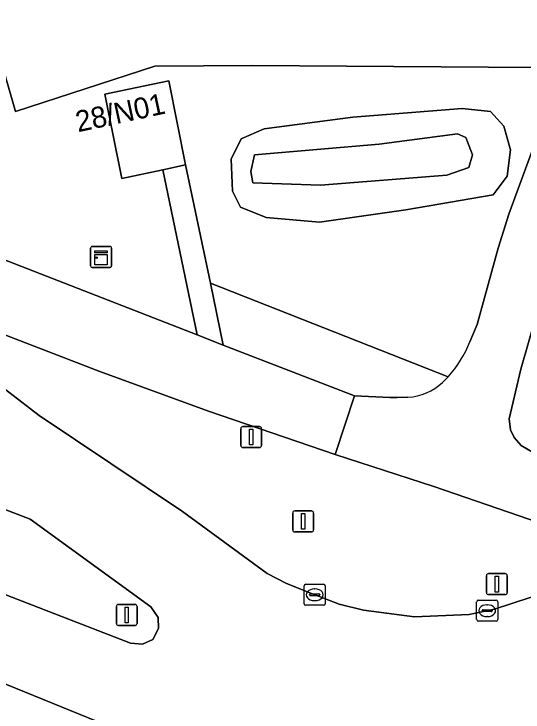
# Model space of a CAD drawing. Extents: x 156141 to 158132, y 385651 to 388333.
# Drawn here: x 156302.91 to 156327.12, y 386506.29 to 386539.53 of the extents above; entities that cross this region are included whole.
import ezdxf

# ---------------------------------------------------------------- set-up
doc = ezdxf.new("R2010")
doc.units = 0
for name, color, linetype in [('IMGEO_Berm_groen', 7, 'Continuous'), ('IMGEO_Bouwland', 7, 'Continuous'), ('IMGEO_Fietspad_gesloten', 7, 'Continuous'), ('IMGEO_Groenvoorziening', 7, 'Continuous'), ('IMGEO_Kast', 7, 'Continuous'), ('IMGEO_Kolk', 7, 'Continuous'), ('IMGEO_Lichtmast', 7, 'Continuous'), ('IMGEO_Pand', 7, 'Continuous'), ('IMGEO_Pand_nummerreeks', 7, 'Continuous'), ('IMGEO_Rijbaan_lokaal_gesloten', 7, 'Continuous'), ('IMGEO_Verkeersbordpaal', 7, 'Continuous'), ('IMGEO_Verkeerseiland_open', 7, 'Continuous'), ('IMGEO_Voetpad_open', 7, 'Continuous')]:
    doc.layers.add(name, color=color, linetype=linetype)

msp = doc.modelspace()

# ---------------------------------------------------------------- linework, layer by layer
at = {"layer": 'IMGEO_Berm_groen'}
for points in [[(156329, 386529.519), (156327.01, 386522.618), (156326.464, 386520.258), (156326.529, 386519.727), (156326.698, 386519.369), (156327.033, 386518.98), (156327.569, 386518.673)], [(156312.247, 386526.707), (156312.861, 386523.766), (156319.111, 386521.349), (156320.786, 386521.275), (156321.133, 386521.268), (156321.646, 386521.284)], [(156323.283, 386521.987), (156323.558, 386522.259), (156312.247, 386526.707)], [(156330.955, 386514.254), (156322.883, 386517.032), (156318.18, 386518.557), (156312.164, 386520.621), (156306.982, 386522.509), (156300.726, 386524.92)], [(156302.029, 386522.003), (156304.102, 386520.406), (156310.923, 386515.834), (156314.943, 386512.888), (156315.868, 386512.406), (156317.104, 386511.915), (156318.366, 386511.435), (156319.539, 386511.139), (156321.96, 386510.826), (156324.552, 386510.938), (156325.767, 386511.191), (156328.331, 386512.037)], [(156312.749, 386503.448), (156300.816, 386508.304), (156300.112, 386507.623), (156298.483, 386509.171), (156297.512, 386509.849), (156296.614, 386510.333), (156294.594, 386511.201), (156294.457, 386511.254), (156293.331, 386511.691), (156280.601, 386516.602), (156280.646, 386516.287), (156293.375, 386511.374), (156294.501, 386510.945), (156294.638, 386510.893), (156295.217, 386510.672), (156294.81, 386509.685), (156294.714, 386509.453), (156294.56, 386509.081), (156293.654, 386509.429), (156280.922, 386514.32), (156281.324, 386511.45), (156294.12, 386506.497), (156295.193, 386506.082)]]:
    msp.add_lwpolyline(points, dxfattribs=at)
msp.add_arc((156321.502, 386523.877), 2.597, 273.1821, 313.2995, dxfattribs=at)
at = {"layer": 'IMGEO_Bouwland'}
msp.add_lwpolyline([(156298.424, 386578.759), (156299.096, 386571.593), (156300.523, 386561.055), (156301.816, 386553.654), (156301.952, 386551.718), (156300.78, 386542.538), (156302.98, 386534.895), (156309.604, 386537.043), (156314.236, 386537.081), (156327.718, 386536.986), (156337.845, 386577.757)], dxfattribs=at)
at = {"layer": 'IMGEO_Fietspad_gesloten'}
for points in [[(156348.163, 386611.714), (156343.943, 386590.004), (156341.252, 386578.081), (156338.908, 386569.228), (156337.052, 386561.839), (156334.06, 386550.854), (156331.742, 386543.951), (156329.901, 386538.856), (156329.08, 386536.913), (156328.367, 386535.225), (156326.447, 386529.996), (156325.935, 386528.385), (156324.936, 386524.744), (156324.596, 386523.924)], [(156327.569, 386518.673), (156327.033, 386518.98), (156326.698, 386519.369), (156326.529, 386519.727), (156326.464, 386520.258), (156327.01, 386522.618), (156329, 386529.519)], [(156323.558, 386522.259), (156323.283, 386521.987)], [(156321.646, 386521.284), (156321.133, 386521.268), (156320.786, 386521.275), (156319.111, 386521.349), (156318.18, 386518.557), (156322.883, 386517.032), (156330.955, 386514.254)]]:
    msp.add_lwpolyline(points, dxfattribs=at)
msp.add_lwpolyline([(156278.184, 386533.831), (156290.97, 386528.872), (156292.011, 386528.468), (156292.144, 386528.416), (156292.75, 386528.181), (156300.726, 386524.92), (156306.982, 386522.509), (156312.164, 386520.621), (156318.18, 386518.557), (156319.111, 386521.349), (156312.861, 386523.766), (156311.622, 386524.249), (156299.915, 386528.814), (156295.216, 386530.406), (156291.691, 386531.601), (156291.559, 386531.654), (156290.488, 386532.081), (156277.717, 386537.157), (156277.717, 386537.157)], close=True, dxfattribs=at)
for centre, radius, start, end in [((156319.467, 386525.966), 5.521, 317.8239, 338.2954), ((156321.502, 386523.877), 2.597, 273.1821, 313.2995)]:
    msp.add_arc(centre, radius, start, end, dxfattribs=at)
at = {"layer": 'IMGEO_Groenvoorziening'}
for points in [[(156324.596, 386523.924), (156324.936, 386524.744), (156325.935, 386528.385), (156326.447, 386529.996), (156328.367, 386535.225), (156329.08, 386536.913), (156327.718, 386536.986), (156314.236, 386537.081), (156309.604, 386537.043), (156302.98, 386534.895), (156300.78, 386542.538), (156301.952, 386551.718), (156301.606, 386551.306), (156300.28, 386551.079), (156300.198, 386551.075), (156298.812, 386551.003), (156297.818, 386551.756), (156295.883, 386563.923), (156294.043, 386576.864)], [(156277.528, 386538.5), (156277.717, 386537.157), (156277.717, 386537.157), (156290.488, 386532.081), (156291.559, 386531.654), (156291.691, 386531.601), (156295.216, 386530.406), (156296.507, 386533.719), (156301.125, 386531.917), (156299.915, 386528.814), (156311.622, 386524.249), (156309.985, 386532.114), (156308.042, 386531.705), (156307.234, 386535.712), (156310.277, 386536.35), (156311.07, 386532.343), (156312.247, 386526.707), (156323.558, 386522.259)]]:
    msp.add_lwpolyline(points, dxfattribs=at)
for points in [[(156321.551, 386530.208), (156325.692, 386530.921), (156326.359, 386531.817), (156326.521, 386533.069), (156326.203, 386534.188), (156325.576, 386534.896), (156324.217, 386535.031), (156319.03, 386534.625), (156314.803, 386534.068), (156313.717, 386533.589), (156313.239, 386532.618), (156313.301, 386531.095), (156313.679, 386530.328), (156314.905, 386529.836), (156317.436, 386529.624)], [(156324.217, 386535.031), (156325.576, 386534.896), (156326.203, 386534.188), (156326.521, 386533.069), (156326.359, 386531.817), (156325.692, 386530.921), (156321.551, 386530.208), (156317.436, 386529.624), (156314.905, 386529.836), (156313.679, 386530.328), (156313.301, 386531.095), (156313.239, 386532.618), (156313.717, 386533.589), (156314.803, 386534.068), (156319.03, 386534.625)], [(156323.498, 386531.855), (156324.54, 386532.22), (156324.723, 386532.819), (156324.395, 386533.645), (156323.996, 386533.828), (156320.273, 386533.334), (156314.349, 386532.826), (156314.165, 386532.027), (156314.267, 386531.49), (156317.48, 386531.375)], [(156317.48, 386531.375), (156314.267, 386531.49), (156314.165, 386532.027), (156314.349, 386532.826), (156320.273, 386533.334), (156323.996, 386533.828), (156324.395, 386533.645), (156324.723, 386532.819), (156324.54, 386532.22), (156323.498, 386531.855)]]:
    msp.add_lwpolyline(points, close=True, dxfattribs=at)
msp.add_arc((156319.467, 386525.966), 5.521, 317.8239, 338.2954, dxfattribs=at)
at = {"layer": 'IMGEO_Kast'}
for p, q in [((156306.55, 386527.536), (156306.55, 386528.377)), ((156306.55, 386528.377), (156306.55, 386527.536)), ((156306.625, 386528.461), (156307.466, 386528.461)), ((156307.466, 386528.461), (156306.625, 386528.461)), ((156307.55, 386528.386), (156307.55, 386527.545)), ((156307.55, 386527.545), (156307.55, 386528.386)), ((156307.475, 386527.461), (156306.634, 386527.461)), ((156306.634, 386527.461), (156307.475, 386527.461))]:
    msp.add_line(p, q, dxfattribs=at)
for points in [[(156306.745, 386528.251), (156307.345, 386528.251), (156307.345, 386528.166), (156306.745, 386528.166), (156306.745, 386528.251)], [(156306.745, 386528.076), (156307.345, 386528.076), (156307.345, 386527.587), (156306.745, 386527.587), (156306.745, 386528.076)]]:
    msp.add_lwpolyline(points, dxfattribs=at)
msp.add_circle((156306.829, 386527.925), 0.0377, dxfattribs=at)
for centre, start, end in [((156306.628, 386528.383), 92.4484, 184.2845), ((156306.628, 386528.383), 92.4484, 184.2845), ((156307.472, 386528.383), 2.4484, 94.2845), ((156307.472, 386528.383), 2.4484, 94.2845), ((156306.628, 386527.539), 182.4484, 274.2845), ((156306.628, 386527.539), 182.4484, 274.2845), ((156307.472, 386527.539), 272.4484, 4.2845), ((156307.472, 386527.539), 272.4484, 4.2845)]:
    msp.add_arc(centre, 0.0779, start, end, dxfattribs=at)
at = {"layer": 'IMGEO_Kolk'}
for p, q in [((156316.784, 386512.375), (156317.636, 386512.375)), ((156316.709, 386511.449), (156316.709, 386512.301)), ((156317.197, 386512.155), (156317.222, 386512.155)), ((156317.71, 386512.301), (156317.71, 386511.449)), ((156316.968, 386511.869), (156316.968, 386511.881)), ((156317.406, 386511.832), (156317.008, 386511.832)), ((156317.011, 386511.918), (156317.409, 386511.918)), ((156317.452, 386511.881), (156317.452, 386511.869)), ((156317.636, 386511.375), (156316.784, 386511.375)), ((156317.22, 386511.595), (156317.195, 386511.595)), ((156324.914, 386510.692), (156324.914, 386511.544)), ((156324.989, 386511.618), (156325.841, 386511.618)), ((156325.402, 386511.398), (156325.427, 386511.398)), ((156325.915, 386511.544), (156325.915, 386510.692)), ((156325.173, 386511.112), (156325.173, 386511.124)), ((156325.611, 386511.075), (156325.213, 386511.075)), ((156325.216, 386511.161), (156325.614, 386511.161)), ((156325.657, 386511.124), (156325.657, 386511.112)), ((156325.425, 386510.838), (156325.4, 386510.838)), ((156325.841, 386510.618), (156324.989, 386510.618))]:
    msp.add_line(p, q, dxfattribs=at)
for points in [[(156316.784, 386512.375), (156317.636, 386512.375)], [(156316.709, 386511.449), (156316.709, 386512.301)], [(156317.71, 386512.301), (156317.71, 386511.449)], [(156317.636, 386511.375), (156316.784, 386511.375)], [(156324.914, 386510.692), (156324.914, 386511.544)], [(156324.989, 386511.618), (156325.841, 386511.618)], [(156325.915, 386511.544), (156325.915, 386510.692)], [(156325.841, 386510.618), (156324.989, 386510.618)]]:
    msp.add_lwpolyline(points, dxfattribs=at)
for centre, radius, start, end in [((156316.786, 386512.299), 0.0765, 91.552, 178.448), ((156316.786, 386512.299), 0.0765, 91.552, 178.448), ((156317.634, 386512.299), 0.0765, 1.552, 88.448), ((156317.634, 386512.299), 0.0765, 1.552, 88.448), ((156317.008, 386511.878), 0.0403, 85.8775, 175.7526), ((156317.005, 386511.868), 0.0366, 178.938, 274.7102), ((156317.409, 386511.875), 0.043, 264.8664, 352.4533), ((156317.413, 386511.88), 0.0386, 1.7309, 96.639), ((156316.786, 386511.451), 0.0765, 181.552, 268.448), ((156316.786, 386511.451), 0.0765, 181.552, 268.448), ((156317.634, 386511.451), 0.0765, 271.552, 358.448), ((156317.634, 386511.451), 0.0765, 271.552, 358.448), ((156324.991, 386511.542), 0.0765, 91.552, 178.448), ((156324.991, 386511.542), 0.0765, 91.552, 178.448), ((156325.839, 386511.542), 0.0765, 1.552, 88.448), ((156325.839, 386511.542), 0.0765, 1.552, 88.448), ((156325.213, 386511.121), 0.0403, 85.8775, 175.7526), ((156325.21, 386511.111), 0.0366, 178.938, 274.7102), ((156325.614, 386511.118), 0.043, 264.8664, 352.4533), ((156325.618, 386511.123), 0.0386, 1.7309, 96.639), ((156324.991, 386510.694), 0.0765, 181.552, 268.448), ((156324.991, 386510.694), 0.0765, 181.552, 268.448), ((156325.839, 386510.694), 0.0765, 271.552, 358.448), ((156325.839, 386510.694), 0.0765, 271.552, 358.448)]:
    msp.add_arc(centre, radius, start, end, dxfattribs=at)
for centre, major_axis, ratio, start_param, end_param in [((156317.196, 386511.875), (-0.387, 0.002), 0.722429, 4.712389, 7.853982), ((156317.221, 386511.875), (-0.39, 0.002), 0.717154, 1.570796, 4.712389), ((156325.401, 386511.118), (-0.387, 0.002), 0.722429, 4.712389, 7.853982), ((156325.426, 386511.118), (-0.39, 0.002), 0.717154, 1.570796, 4.712389)]:
    msp.add_ellipse(centre, major_axis=major_axis, ratio=ratio, start_param=start_param, end_param=end_param, dxfattribs=at)
at = {"layer": 'IMGEO_Lichtmast'}
for p, q in [((156307.874, 386511.414), (156308.664, 386511.414)), ((156308.664, 386511.414), (156307.874, 386511.414)), ((156307.774, 386510.514), (156307.774, 386511.314)), ((156307.774, 386511.314), (156307.774, 386510.514)), ((156308.764, 386511.314), (156308.764, 386510.514)), ((156308.764, 386510.514), (156308.764, 386511.314)), ((156308.664, 386510.414), (156307.874, 386510.414)), ((156307.874, 386510.414), (156308.664, 386510.414))]:
    msp.add_line(p, q, dxfattribs=at)
msp.add_lwpolyline([(156308.194, 386511.289), (156308.344, 386511.289), (156308.344, 386510.539), (156308.194, 386510.539), (156308.194, 386511.289)], dxfattribs=at)
for centre, start, end in [((156307.874, 386511.314), 90, 180), ((156307.874, 386511.314), 90, 180), ((156308.664, 386511.314), 0, 90), ((156308.664, 386511.314), 360, 90), ((156307.874, 386510.514), 180, 270), ((156307.874, 386510.514), 180, 270), ((156308.664, 386510.514), 270, 0), ((156308.664, 386510.514), 270, 0)]:
    msp.add_arc(centre, 0.1, start, end, dxfattribs=at)
at = {"layer": 'IMGEO_Pand'}
msp.add_lwpolyline([(156311.07, 386532.343), (156310.277, 386536.35), (156307.234, 386535.712), (156308.042, 386531.705), (156309.985, 386532.114)], close=True, dxfattribs=at)
at = {"layer": 'IMGEO_Rijbaan_lokaal_gesloten'}
for points in [[(156278.561, 386531.142), (156279.45, 386524.804), (156292.191, 386519.892), (156293.29, 386519.47), (156293.425, 386519.418), (156303.669, 386515.482), (156309.414, 386511.3), (156309.768, 386510.799), (156309.786, 386510.272), (156309.503, 386509.752), (156309.018, 386509.516), (156308.448, 386509.57), (156294.031, 386515.158), (156293.895, 386515.211), (156292.782, 386515.644), (156280.043, 386520.581), (156280.191, 386519.527), (156280.571, 386516.818), (156293.303, 386511.894), (156294.428, 386511.458), (156294.565, 386511.405), (156300.87, 386508.862), (156300.816, 386508.304), (156312.749, 386503.448)], [(156338.735, 386515.452), (156334.214, 386516.809), (156331.099, 386513.557), (156329.596, 386512.65), (156328.331, 386512.037), (156325.767, 386511.191), (156324.552, 386510.938), (156321.96, 386510.826), (156319.539, 386511.139), (156318.366, 386511.435), (156317.104, 386511.915), (156315.868, 386512.406), (156314.943, 386512.888), (156310.923, 386515.834), (156304.102, 386520.406), (156302.029, 386522.003), (156301.502, 386521.067), (156297.884, 386523.073), (156294.684, 386524.679), (156292.549, 386525.572), (156292.415, 386525.628), (156291.362, 386526.06), (156278.561, 386531.142)]]:
    msp.add_lwpolyline(points, dxfattribs=at)
at = {"layer": 'IMGEO_Verkeersbordpaal'}
for p, q in [((156313.694, 386518.984), (156313.694, 386519.784)), ((156313.694, 386519.784), (156313.694, 386518.984)), ((156313.794, 386519.884), (156314.584, 386519.884)), ((156314.584, 386519.884), (156313.794, 386519.884)), ((156314.684, 386519.784), (156314.684, 386518.984)), ((156314.684, 386518.984), (156314.684, 386519.784)), ((156314.584, 386518.884), (156313.794, 386518.884)), ((156313.794, 386518.884), (156314.584, 386518.884)), ((156316.163, 386514.967), (156316.163, 386515.767)), ((156316.163, 386515.767), (156316.163, 386514.967)), ((156316.263, 386515.867), (156317.053, 386515.867)), ((156317.053, 386515.867), (156316.263, 386515.867)), ((156317.153, 386515.767), (156317.153, 386514.967)), ((156317.153, 386514.967), (156317.153, 386515.767)), ((156317.053, 386514.867), (156316.263, 386514.867)), ((156316.263, 386514.867), (156317.053, 386514.867)), ((156325.377, 386511.981), (156325.377, 386512.781)), ((156325.377, 386512.781), (156325.377, 386511.981)), ((156325.477, 386512.881), (156326.267, 386512.881)), ((156326.267, 386512.881), (156325.477, 386512.881)), ((156326.367, 386512.781), (156326.367, 386511.981)), ((156326.367, 386511.981), (156326.367, 386512.781)), ((156326.267, 386511.881), (156325.477, 386511.881)), ((156325.477, 386511.881), (156326.267, 386511.881))]:
    msp.add_line(p, q, dxfattribs=at)
for points in [[(156314.114, 386519.759), (156314.264, 386519.759), (156314.264, 386519.009), (156314.114, 386519.009), (156314.114, 386519.759)], [(156316.583, 386515.742), (156316.733, 386515.742), (156316.733, 386514.992), (156316.583, 386514.992), (156316.583, 386515.742)], [(156325.797, 386512.756), (156325.947, 386512.756), (156325.947, 386512.006), (156325.797, 386512.006), (156325.797, 386512.756)]]:
    msp.add_lwpolyline(points, dxfattribs=at)
for centre, start, end in [((156313.794, 386519.784), 90, 180), ((156313.794, 386519.784), 90, 180), ((156314.584, 386519.784), 0, 90), ((156314.584, 386519.784), 360, 90), ((156313.794, 386518.984), 180, 270), ((156313.794, 386518.984), 180, 270), ((156314.584, 386518.984), 270, 0), ((156314.584, 386518.984), 270, 0), ((156316.263, 386515.767), 90, 180), ((156316.263, 386515.767), 90, 180), ((156317.053, 386515.767), 0, 90), ((156317.053, 386515.767), 360, 90), ((156316.263, 386514.967), 180, 270), ((156316.263, 386514.967), 180, 270), ((156317.053, 386514.967), 270, 0), ((156317.053, 386514.967), 270, 0), ((156325.477, 386512.781), 90, 180), ((156325.477, 386512.781), 90, 180), ((156326.267, 386512.781), 0, 90), ((156326.267, 386512.781), 360, 90), ((156325.477, 386511.981), 180, 270), ((156325.477, 386511.981), 180, 270), ((156326.267, 386511.981), 270, 0), ((156326.267, 386511.981), 270, 0)]:
    msp.add_arc(centre, 0.1, start, end, dxfattribs=at)
at = {"layer": 'IMGEO_Verkeerseiland_open'}
msp.add_lwpolyline([(156279.45, 386524.804), (156280.043, 386520.581), (156292.782, 386515.644), (156293.895, 386515.211), (156294.031, 386515.158), (156308.448, 386509.57), (156309.018, 386509.516), (156309.503, 386509.752), (156309.786, 386510.272), (156309.768, 386510.799), (156309.414, 386511.3), (156303.669, 386515.482), (156293.425, 386519.418), (156293.29, 386519.47), (156292.191, 386519.892)], close=True, dxfattribs=at)
at = {"layer": 'IMGEO_Voetpad_open'}
msp.add_lwpolyline([(156312.861, 386523.766), (156312.247, 386526.707), (156311.07, 386532.343), (156309.985, 386532.114), (156311.622, 386524.249)], close=True, dxfattribs=at)

# ---------------------------------------------------------------- texts
at = {"layer": 'IMGEO_Pand_nummerreeks'}
msp.add_text('28/N01', height=1, rotation=12.0948, dxfattribs=at).set_placement((156305.951, 386533.898))

doc.saveas('drawing.dxf')
